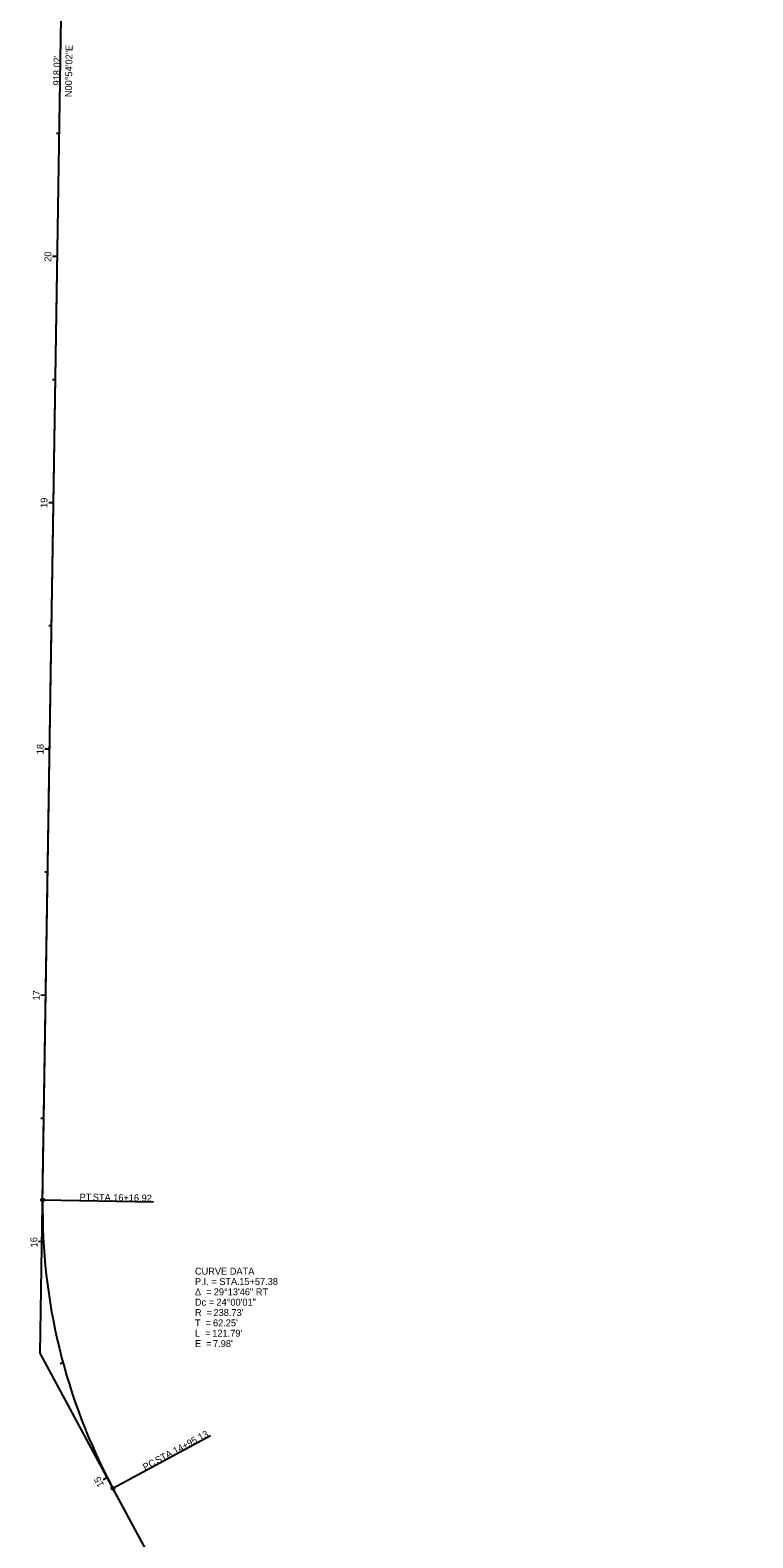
# Model space of a CAD drawing. Extents: x 140402 to 140969, y 345095 to 350073.
# Drawn here: x 140427 to 140721, y 346336 to 346948 of the extents above; entities that cross this region are included whole.
import ezdxf

# ---------------------------------------------------------------- set-up
doc = ezdxf.new("R2010")
doc.units = 0
for name, color, linetype in [('_CIVIL_CONSTRUCTION', 7, 'Continuous'), ('DR_X_Cells', 7, 'Continuous'), ('SC_Scratch1', 7, 'Continuous'), ('SN_X_Public', 7, 'Continuous'), ('SV_X_Control_Cells_Found', 7, 'Continuous'), ('SV_X_Mon_Cells_Found', 7, 'Continuous'), ('SV_X_Shot_Marker', 7, 'Continuous')]:
    doc.layers.add(name, color=color, linetype=linetype)

msp = doc.modelspace()

# ---------------------------------------------------------------- linework, layer by layer
at = {"layer": 'SC_Scratch1'}
for p, q in [((140432.44, 346472.94), (140477.44, 346472.23)), ((140461, 346355.9), (140500.61, 346377.26))]:
    msp.add_line(p, q, dxfattribs=at)
for centre in [(140432.44, 346472.94), (140461, 346355.9)]:
    msp.add_circle(centre, 0.6, dxfattribs=at)
at = {"layer": 'SN_X_Public'}
for p, q in [((140439.25, 346905.97), (140438.05, 346905.98)), ((140438.46, 346855.97), (140436.46, 346856)), ((140437.68, 346805.98), (140436.48, 346806)), ((140436.89, 346755.98), (140434.89, 346756.01)), ((140436.1, 346705.99), (140434.9, 346706.01)), ((140435.32, 346656), (140433.32, 346656.03)), ((140434.53, 346606), (140433.33, 346606.02)), ((140433.75, 346556.01), (140431.75, 346556.04)), ((140432.96, 346506.01), (140431.76, 346506.03)), ((140432.77, 346456.03), (140430.78, 346455.92)), ((140440.72, 346406.75), (140439.56, 346406.44)), ((140458.74, 346360.21), (140456.96, 346359.3))]:
    msp.add_line(p, q, dxfattribs=at)
at = {"layer": 'SV_X_Control_Cells_Found'}
for p, q in [((140431.46, 346410.7), (140446.87, 347390.84)), ((140720.96, 345873.69), (140431.46, 346410.7))]:
    msp.add_line(p, q, dxfattribs=at)
msp.add_arc((140671.14, 346469.19), 238.73, 179.09948, 208.32904, dxfattribs=at)
at = {"layer": 'SV_X_Mon_Cells_Found'}
for p, q in [((140432.44, 346472.94), (140446.87, 347390.84)), ((140648.71, 346007.71), (140461, 346355.9))]:
    msp.add_line(p, q, dxfattribs=at)
msp.add_arc((140671.14, 346469.19), 238.73, 179.09948, 208.32904, dxfattribs=at)

# ---------------------------------------------------------------- texts
at = {"layer": '_CIVIL_CONSTRUCTION'}
msp.add_text('N00°54\'02"E', height=2.8, rotation=89.09948, dxfattribs=at).set_placement((140444.28, 346920.7))
at = {"layer": 'DR_X_Cells'}
msp.add_text("918.02'", height=2.8, rotation=89.09948, dxfattribs=at).set_placement((140439.52, 346925.45))
at = {"layer": 'SC_Scratch1'}
for s, rotation, p in [('PT', 359.09948, (140447.4, 346472.74)), (' STA. ', 359.09948, (140451.75, 346472.67)), ('16+16.92', 359.09948, (140461.07, 346472.53)), ('14+95.13', 28.32904, (140486.31, 346369.59)), ('PC', 28.32904, (140474.06, 346362.98)), (' STA. ', 28.32904, (140478.11, 346365.16))]:
    msp.add_text(s, height=2.8, rotation=rotation, dxfattribs=at).set_placement(p)
at = {"layer": 'SN_X_Public'}
for s, rotation, p in [('20', 89.09948, (140435.93, 346853.86)), ('19', 89.09948, (140434.36, 346753.91)), ('18', 89.09948, (140432.78, 346653.9)), ('17', 89.09948, (140431.21, 346553.92)), ('16', 93.16065, (140430.4, 346453.75)), ('15', 117.16089, (140457.47, 346357.21))]:
    msp.add_text(s, height=2.8, rotation=rotation, dxfattribs=at).set_placement(p)
at = {"layer": 'SV_X_Shot_Marker'}
for s, p in [('CURVE DATA', (140494.3, 346442.62)), ('P.I. = STA. ', (140494.3, 346438.42)), ('15+57.38', (140512.3, 346438.42)), ('Δ  = ', (140494.3, 346434.22)), ('Dc = ', (140494.3, 346430.02)), ('29°13\'46" RT', (140501.95, 346434.22)), ('24°00\'01"', (140503.05, 346430.02)), ('R  = ', (140494.3, 346425.82)), ("238.73'", (140501.84, 346425.82)), ('T  = ', (140494.3, 346421.62)), ("62.25'", (140501.62, 346421.62)), ('L  = ', (140494.3, 346417.42)), ('E  = ', (140494.3, 346413.22)), ("121.79'", (140501.34, 346417.42)), ("7.98'", (140501.65, 346413.22))]:
    msp.add_text(s, height=2.8, dxfattribs=at).set_placement(p)

doc.saveas('drawing.dxf')
